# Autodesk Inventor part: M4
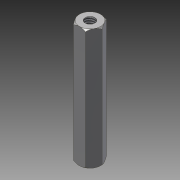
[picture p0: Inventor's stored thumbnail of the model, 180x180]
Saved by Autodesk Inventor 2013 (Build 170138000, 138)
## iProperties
Created: 2012-08
Part Number: M4
Material: Stahl
Document SubType Name: Modeling
Designer: rYan
Density: 7.85 g/cm^3
Author: rYan
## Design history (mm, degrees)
derived "Abstandsbolzen Typ A.ipt"
feature "Volumenkörper1::Abstandsbolzen Typ A.ipt"
tag "Bezeichnung1"
node "Volumenkörper1"
other parameters: "SW" = 7, "d2" = 0, "d16" = 45 deg
